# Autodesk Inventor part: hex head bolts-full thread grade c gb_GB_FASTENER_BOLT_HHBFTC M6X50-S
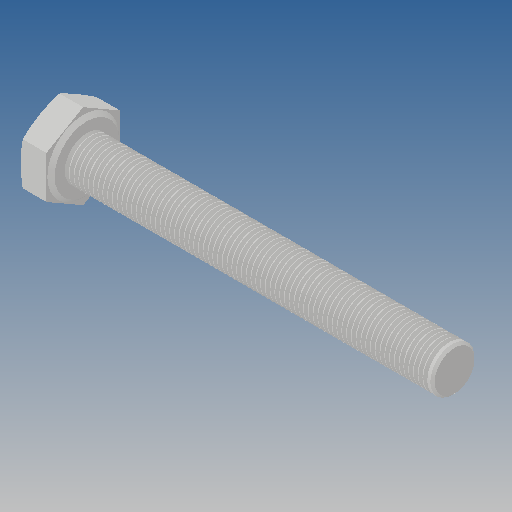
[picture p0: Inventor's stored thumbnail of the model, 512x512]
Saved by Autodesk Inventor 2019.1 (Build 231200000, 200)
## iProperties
Created: 2017-10
Part Number: hex head bolts-full thread grade c gb_GB_FASTENER_BOLT_HHBFTC M6X50-S
Material: Ogólny
Document SubType Name: Modeling
Designer: CADENGINEERING4
Density: 1 g/cm^3
Appearance: Domyślna
Author: CADENGINEERING4
Revision Number: ÈÎºÎ
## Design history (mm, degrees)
feature "LPattern10"
node "Bryła1"
